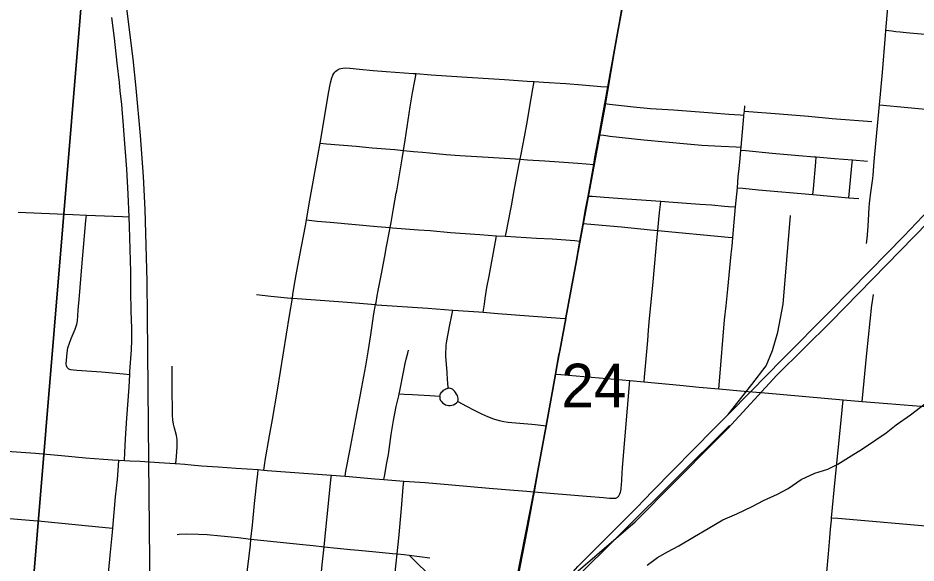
# Model space of a CAD drawing. Extents: x 0 to 1067, y 0 to 440.
# Drawn here: x 348.6 to 400.3, y 135.7 to 167.1 of the extents above; entities that cross this region are included whole.
import ezdxf

# ---------------------------------------------------------------- set-up
doc = ezdxf.new("R2010")
doc.units = 0
for name, color, linetype in [('Default', 7, 'Continuous'), ('GM_X_City_Street', 7, 'Continuous'), ('GM_X_Minor_River', 7, 'Continuous'), ('GM_X_Rail_Line', 7, 'Continuous'), ('GM_X_Section', 7, 'Continuous'), ('GM_X_Section_Text', 7, 'Continuous'), ('GM_X_US_Route', 7, 'Continuous')]:
    doc.layers.add(name, color=color, linetype=linetype)

msp = doc.modelspace()

# ---------------------------------------------------------------- linework, layer by layer
at = {"layer": 'Default'}
for points in [[(383.538, 168.597), (383.153, 166.431), (382.55, 163.126), (382.375, 162.166), (382.243, 161.443), (382.049, 160.376), (381.811, 159.058), (381.741, 158.671), (381.413, 156.85), (381.256, 155.976), (381.129, 155.274), (380.944, 154.262), (380.743, 153.151), (380.135, 149.851), (380.126, 149.804), (379.785, 147.945), (379.742, 147.712)], [(379.742, 147.712), (379.542, 146.607), (379.384, 145.736), (379.002, 143.629), (378.534, 141.049), (378.311, 139.839), (378.257, 139.545), (377.888, 137.567), (377.514, 135.589), (377.361, 134.784), (377.174, 133.774), (377.049, 133.098), (376.913, 132.365), (376.752, 131.513), (376.559, 130.556), (376.489, 130.238), (376.345, 129.588), (376.17, 128.796), (376.116, 128.559)]]:
    msp.add_lwpolyline(points, dxfattribs=at)
at = {"layer": 'GM_X_City_Street'}
for p, q in [((383.819, 146.248), (384.641, 146.171)), ((391.585, 145.523), (396.085, 145.133)), ((396.085, 145.133), (397.164, 145.035))]:
    msp.add_line(p, q, dxfattribs=at)
for points in [[(397.42, 154.116), (397.459, 154.413), (397.5, 154.855), (397.534, 155.438), (397.554, 155.842), (397.579, 156.174), (397.603, 156.432), (397.632, 156.727), (397.653, 156.911), (397.728, 157.46), (397.779, 157.864), (397.797, 158.049), (397.86, 158.829), (397.973, 160.09), (398.165, 162.1), (398.341, 163.948), (398.511, 166.102), (398.535, 166.376), (398.766, 169.034), (398.795, 169.336), (399.007, 171.556), (399.088, 172.671), (399.285, 174.937), (399.299, 175.099)], [(354.761, 141.641), (354.783, 142.094), (354.821, 142.876), (354.895, 144.069), (355.028, 145.853), (355.065, 146.588), (355.074, 146.751), (355.168, 148.011), (355.189, 148.567), (355.182, 149.235), (355.14, 150.242), (355.124, 151.362), (355.118, 152.481), (355.055, 155.09), (355.033, 155.659), (354.983, 156.952), (354.892, 158.403), (354.742, 160.374), (354.68, 161.154), (354.643, 161.599), (354.6, 162.119), (354.522, 162.896), (354.468, 163.377), (354.346, 164.489), (354.187, 165.932), (354.03, 167.113)], [(401.848, 166.045), (399.699, 166.237), (399.364, 166.272), (399.109, 166.3), (398.876, 166.329), (398.535, 166.376)], [(367.047, 164.138), (367.124, 164.173), (367.208, 164.194), (367.314, 164.212), (367.462, 164.219), (367.719, 164.211), (368.274, 164.153), (369.056, 164.077), (369.8, 164.018), (371.359, 163.908), (371.527, 163.895), (372.393, 163.831), (374.157, 163.708), (375.386, 163.629), (376.613, 163.548), (377.916, 163.467), (378.309, 163.443), (378.846, 163.409), (380.144, 163.318), (381.073, 163.251), (382.153, 163.159), (382.55, 163.126)], [(362.778, 141.083), (362.836, 141.49), (362.858, 141.637), (363.095, 143.05), (363.263, 143.991), (363.554, 145.674), (364.242, 149.974), (364.413, 150.974), (364.449, 151.185), (364.526, 151.662), (364.635, 152.322), (364.847, 153.457), (365.164, 155.141), (365.224, 155.488), (365.42, 156.61), (365.828, 158.845), (366.014, 159.89), (366.155, 160.68), (366.498, 162.777), (366.609, 163.358), (366.681, 163.642), (366.746, 163.809), (366.79, 163.892), (366.853, 163.97), (366.908, 164.035), (366.983, 164.095), (367.047, 164.138)], [(367.443, 140.733), (367.496, 141.021), (367.713, 142.194), (368.058, 144.028), (368.328, 145.441), (368.408, 145.849), (368.525, 146.47), (368.641, 147.085), (368.772, 147.883), (368.927, 148.872), (369.104, 150.068), (369.199, 150.602), (369.222, 150.732), (369.296, 151.101), (369.354, 151.424), (369.545, 152.369), (369.737, 153.393), (369.831, 153.944), (369.993, 154.823), (370.034, 155.033), (370.092, 155.335), (370.152, 155.664), (370.234, 156.139), (370.385, 157.018), (370.413, 157.159), (370.573, 158.071), (370.732, 158.989), (370.811, 159.471), (370.908, 160.056), (371.193, 161.973), (371.326, 162.782), (371.452, 163.48), (371.527, 163.895)], [(376.667, 154.532), (376.739, 154.9), (376.782, 155.12), (377.009, 156.292), (377.16, 157.175), (377.435, 158.605), (377.511, 158.974), (377.572, 159.263), (377.755, 160.254), (377.884, 160.989), (378.136, 162.462), (378.233, 163.012), (378.309, 163.443)], [(382.375, 162.166), (382.652, 162.136), (384.032, 161.987), (384.994, 161.895), (386.335, 161.807), (388.568, 161.64), (389.5, 161.568), (390.167, 161.518), (390.377, 161.502)], [(388.931, 145.758), (388.967, 146.191), (389.264, 149.721), (389.348, 150.536), (389.447, 151.501), (389.639, 153.504), (389.691, 153.959), (389.732, 154.467), (389.896, 156.227), (389.998, 157.325), (390.051, 157.98), (390.095, 158.423), (390.155, 159.012), (390.198, 159.491), (390.213, 159.66), (390.37, 161.427), (390.377, 161.502), (390.398, 161.736), (390.425, 162.047)], [(390.398, 161.736), (392.412, 161.588), (394.081, 161.437), (395.453, 161.318), (397.724, 161.146)], [(398.165, 162.1), (401.435, 161.798)], [(382.049, 160.376), (382.315, 160.343), (382.664, 160.299), (384.627, 160.081), (387.114, 159.847), (387.954, 159.776), (389.074, 159.712), (389.925, 159.673), (390.213, 159.66)], [(366.014, 159.89), (366.373, 159.859), (368.08, 159.711), (369.006, 159.627), (370.303, 159.519), (370.811, 159.471), (371.374, 159.417), (371.886, 159.371), (372.304, 159.333), (373.263, 159.244), (374.04, 159.185), (375.336, 159.109), (376.933, 159.017), (377.511, 158.974), (377.934, 158.942), (378.937, 158.868), (379.755, 158.813), (380.833, 158.743), (381.312, 158.705), (381.741, 158.671)], [(390.198, 159.491), (390.491, 159.462), (392.005, 159.311), (393.532, 159.189), (394.425, 159.11), (394.525, 159.102), (395.58, 159.016), (396.614, 158.932), (397.479, 158.861)], [(394.345, 156.934), (394.372, 157.255), (394.5, 158.8), (394.525, 159.102)], [(396.409, 156.752), (396.446, 157.144), (396.582, 158.593), (396.614, 158.932)], [(389.998, 157.325), (390.31, 157.296), (391.203, 157.211), (394.345, 156.934), (396.409, 156.752), (396.972, 156.703)], [(381.413, 156.85), (381.646, 156.836), (382.347, 156.793), (383.647, 156.69), (385.601, 156.557), (386.062, 156.525), (387.845, 156.392), (388.513, 156.337), (389.255, 156.273), (389.478, 156.257), (389.896, 156.227)], [(384.641, 146.171), (384.664, 146.432), (384.849, 148.543), (384.893, 149.138), (384.952, 149.807), (385.146, 151.698), (385.259, 152.997), (385.371, 154.298), (385.426, 154.863), (385.489, 155.5), (385.526, 155.896), (385.58, 156.371), (385.601, 156.557)], [(348.659, 155.919), (351.802, 155.789), (352.573, 155.758), (354.641, 155.675), (355.033, 155.659)], [(351.547, 146.914), (351.466, 146.989), (351.419, 147.088), (351.406, 147.199), (351.463, 147.83), (351.511, 148.124), (351.696, 148.651), (351.93, 149.199), (352.026, 149.48), (352.054, 149.663), (352.098, 150.294), (352.174, 151.109), (352.315, 152.78), (352.457, 154.562), (352.543, 155.452), (352.573, 155.758)], [(365.224, 155.488), (365.69, 155.432), (365.838, 155.414), (366.581, 155.34), (369.285, 155.096), (370.034, 155.033), (370.176, 155.021), (371.66, 154.912), (372.328, 154.862), (373.514, 154.755), (375.183, 154.628), (376.15, 154.563), (376.667, 154.532), (377.264, 154.496), (378.454, 154.436), (379.345, 154.386), (380.657, 154.284), (380.944, 154.262)], [(381.129, 155.274), (381.346, 155.255), (383.339, 155.08), (385.01, 154.907), (385.426, 154.863), (389.472, 154.491), (389.732, 154.467)], [(375.374, 150.161), (375.434, 150.511), (375.452, 150.621), (375.506, 150.952), (375.602, 151.58), (375.725, 152.241), (376.088, 154.227), (376.15, 154.563)], [(362.354, 151.178), (363.174, 151.093), (364.323, 150.983), (364.413, 150.974), (367.071, 150.774), (367.815, 150.717), (369.199, 150.602), (369.263, 150.597), (372.202, 150.402), (373.631, 150.291), (375.14, 150.181), (375.374, 150.161), (376.217, 150.089), (378.002, 149.952), (379.815, 149.825), (380.126, 149.804)], [(397.164, 145.035), (397.433, 147.809), (397.727, 150.576), (397.76, 150.785), (397.786, 150.927), (397.803, 151.055), (397.822, 151.195)], [(373.25, 148.096), (373.265, 148.258), (373.284, 148.407), (373.454, 149.353), (373.578, 150.006), (373.631, 150.291)], [(369.677, 140.537), (369.726, 140.814), (369.83, 141.4), (369.933, 141.986), (370.1, 143.127), (370.193, 143.715), (370.227, 143.935), (370.304, 144.331), (370.384, 144.737), (370.532, 145.351), (370.559, 145.474), (370.595, 145.642), (370.812, 146.711), (370.906, 147.207), (370.962, 147.459), (371.043, 147.814), (371.084, 147.986)], [(373.917, 145.027), (373.939, 145.121), (373.939, 145.21), (373.923, 145.287), (373.901, 145.367), (373.856, 145.453), (373.796, 145.547), (373.74, 145.619), (373.685, 145.68), (373.613, 145.735), (373.565, 145.763), (373.498, 145.785), (373.436, 145.795), (373.37, 145.795), (373.353, 146.114), (373.335, 146.284), (373.31, 146.691), (373.243, 147.632), (373.243, 147.867), (373.25, 148.096)], [(351.547, 146.914), (351.656, 146.875), (351.84, 146.855), (352.028, 146.842), (353.444, 146.734), (354.697, 146.622), (355.065, 146.588)], [(357.715, 141.457), (357.751, 141.858), (357.8, 142.414), (357.8, 142.667), (357.783, 142.85), (357.746, 143.067), (357.616, 143.575), (357.586, 143.723), (357.543, 143.985), (357.529, 144.249), (357.507, 145.934), (357.497, 147.056)], [(379.542, 146.607), (379.856, 146.58), (383.819, 146.248)], [(383.089, 139.511), (383.129, 139.541), (383.162, 139.573), (383.207, 139.641), (383.246, 139.719), (383.28, 139.809), (383.299, 139.894), (383.314, 139.978), (383.326, 140.084), (383.336, 140.207), (383.389, 141.239), (383.819, 146.248)], [(384.641, 146.171), (386.691, 145.979), (387.794, 145.861), (388.931, 145.758)], [(372.884, 145.337), (372.904, 145.416), (372.932, 145.478), (372.962, 145.523), (373.011, 145.58), (373.055, 145.624), (373.11, 145.674), (373.177, 145.718), (373.237, 145.757), (373.304, 145.784), (373.37, 145.795)], [(388.931, 145.758), (390.388, 145.626), (391.585, 145.523)], [(370.559, 145.474), (370.833, 145.458), (371.317, 145.431), (372.315, 145.381), (372.884, 145.337), (372.884, 145.271), (372.9, 145.188), (372.939, 145.094), (372.989, 145.022), (373.053, 144.95), (373.143, 144.889), (373.221, 144.845), (373.304, 144.818), (373.392, 144.801), (373.48, 144.801), (373.583, 144.812), (373.68, 144.842), (373.779, 144.889), (373.851, 144.945), (373.917, 145.027), (374.182, 144.895), (374.427, 144.766), (374.857, 144.539), (375.284, 144.312), (375.624, 144.161), (375.972, 144.028), (376.295, 143.935), (376.567, 143.877), (376.825, 143.835), (377.031, 143.815), (378.184, 143.722), (378.37, 143.702), (378.546, 143.682), (379.002, 143.629)], [(394.854, 131.975), (394.877, 132.22), (395.027, 133.828), (395.169, 135.422), (395.238, 136.262), (395.308, 137.179), (395.344, 137.694), (395.406, 138.21), (395.418, 138.347), (395.625, 140.528), (395.961, 143.933), (396.085, 145.133)], [(397.164, 145.035), (398.622, 144.91), (401.988, 144.639), (403.61, 144.497), (406.184, 144.271)], [(346.603, 142.271), (348.831, 142.122), (349.649, 142.056), (351.133, 141.923), (352.528, 141.788), (354.07, 141.675), (354.441, 141.657), (354.761, 141.641), (355.075, 141.625), (355.67, 141.593), (356.748, 141.525), (357.674, 141.46), (357.715, 141.457), (358.223, 141.417), (358.593, 141.385), (359.183, 141.334), (360.147, 141.272), (361.191, 141.196), (362.452, 141.109), (362.778, 141.083), (362.971, 141.068), (366.659, 140.791), (367.443, 140.733), (367.675, 140.713), (369.158, 140.576), (369.677, 140.537), (370.817, 140.452), (372.057, 140.362), (373.577, 140.227), (375.732, 140.044), (377.142, 139.931), (377.887, 139.873), (378.311, 139.839)], [(352.306, 118.96), (352.323, 119.189), (352.375, 119.899), (352.503, 121.16), (352.618, 122.271), (352.678, 122.924), (352.693, 123.087), (352.853, 124.905), (353.016, 126.572), (353.117, 127.608), (353.216, 128.647), (353.298, 129.499), (353.449, 131.13), (353.546, 132.206), (353.686, 133.531), (353.703, 133.689), (353.938, 136.172), (354.068, 137.506), (354.09, 137.748), (354.253, 139.547), (354.355, 140.548), (354.416, 141.332), (354.441, 141.657)], [(361.766, 134.739), (361.998, 136.788), (362.034, 137.11), (362.123, 137.919), (362.238, 139.162), (362.393, 140.563), (362.423, 140.842), (362.452, 141.109)], [(364.764, 121.631), (364.785, 121.875), (364.865, 122.791), (364.869, 122.831), (364.89, 123.218), (364.96, 124.109), (365.071, 125.258), (365.212, 126.629), (365.296, 127.562), (365.309, 127.705), (365.367, 128.272), (365.533, 129.889), (365.743, 131.849), (365.813, 132.503), (365.963, 133.886), (366.133, 135.626), (366.236, 136.674), (366.354, 137.865), (366.457, 138.781), (366.632, 140.525), (366.659, 140.791)], [(369.35, 132.081), (369.636, 132.347), (369.786, 132.513), (369.923, 132.69), (370, 132.818), (370.06, 132.954), (370.097, 133.068), (370.123, 133.167), (370.163, 133.387), (370.311, 135.022), (370.381, 135.727), (370.436, 136.263), (370.528, 137.175), (370.683, 138.884), (370.788, 140.109), (370.817, 140.452)], [(378.311, 139.839), (381.321, 139.589), (382.297, 139.5), (382.645, 139.466), (382.791, 139.461), (382.864, 139.461), (382.932, 139.465), (383.01, 139.478), (383.053, 139.492), (383.089, 139.511)], [(335.65, 139.404), (335.951, 139.377), (339.567, 139.051), (340.386, 138.984), (340.511, 138.974), (340.978, 138.936), (342.092, 138.84), (344.018, 138.654), (349.998, 138.146), (353.662, 137.79), (354.09, 137.748)], [(395.418, 138.347), (395.767, 138.317), (397.328, 138.185), (402.576, 137.729), (403.985, 137.62), (405.558, 137.468), (406.789, 137.35), (408.315, 137.216), (408.613, 137.201), (408.945, 137.206), (409.064, 137.219), (409.195, 137.252), (409.277, 137.301)], [(357.8, 137.375), (357.903, 137.391), (358.305, 137.41), (359.008, 137.401), (359.524, 137.372), (360.298, 137.31), (360.519, 137.288), (360.888, 137.248), (361.294, 137.201), (362.034, 137.11), (362.218, 137.087), (365.023, 136.8), (365.615, 136.74), (366.236, 136.674), (366.986, 136.599), (367.763, 136.52), (368.207, 136.473), (369.207, 136.373), (370.171, 136.289), (370.436, 136.263), (370.838, 136.224), (371.126, 136.188), (372.318, 136.042)], [(371.126, 136.188), (371.196, 136.121), (372.504, 134.831), (373.862, 133.451), (374.599, 132.716), (374.892, 132.451), (375.025, 132.34), (375.191, 132.212), (375.33, 132.111), (375.58, 131.985), (375.936, 131.818), (376.328, 131.671), (376.752, 131.513)]]:
    msp.add_lwpolyline(points, dxfattribs=at)
at = {"layer": 'GM_X_Minor_River'}
msp.add_lwpolyline([(384.802, 135.61), (385.396, 136.06), (385.989, 136.374), (386.627, 136.733), (387.54, 137.272), (388.315, 137.721), (389.159, 138.215), (389.957, 138.572), (390.845, 138.998), (391.507, 139.334), (392.304, 139.691), (392.92, 140.028), (393.673, 140.545), (394.448, 140.903), (395.199, 141.147), (395.768, 141.416), (396.544, 141.91), (397.183, 142.315), (397.959, 142.832), (398.553, 143.237), (399.124, 143.687), (399.946, 144.272), (400.769, 144.903)], dxfattribs=at)
at = {"layer": 'GM_X_Rail_Line'}
msp.add_line((389.553, 143.652), (378.756, 132.93), dxfattribs=at)
for points in [[(376.58, 131.044), (378.327, 140.014), (382.376, 161.87), (384, 171.502)], [(356.264, 129.575), (356.216, 135.845), (356.168, 141.611), (356.111, 147.881), (356.068, 151.953), (355.943, 156.072), (355.856, 157.983), (355.679, 160.335), (355.439, 163.053), (355.264, 164.735), (354.629, 169.803)], [(389.458, 143.485), (392.267, 146.546), (395.371, 149.61), (403.354, 157.796), (407.091, 161.624), (409.522, 164.625), (412.954, 168.924)], [(389.459, 144.278), (390.77, 145.605), (392.599, 147.461), (395.341, 150.233), (397.597, 152.528), (399.565, 154.533), (401.022, 156.077), (402.126, 157.297), (404.132, 159.609), (405.12, 160.763), (405.985, 161.836), (408.574, 165.069)], [(389.459, 144.278), (390.835, 146), (391.644, 147.085), (392.019, 147.973), (392.315, 149.019), (392.631, 150.636), (393.045, 155.726)], [(378.756, 132.93), (379.015, 133.243), (380.156, 134.762), (380.835, 135.535), (381.635, 136.353), (382.569, 137.287), (384.209, 138.923), (385.126, 139.88), (388.671, 143.48), (389.459, 144.278)], [(384.114, 138.104), (388.684, 142.711), (389.458, 143.485)], [(379.945, 134.531), (381.122, 135.514), (384.114, 138.104)]]:
    msp.add_lwpolyline(points, dxfattribs=at)
at = {"layer": 'GM_X_Section'}
for points in [[(293.305, 184.745), (353.183, 178.942), (348.264, 119.585), (289.359, 125.481)], [(353.183, 178.942), (415.565, 173.729), (410.18, 114.397), (348.264, 119.585)]]:
    msp.add_lwpolyline(points, close=True, dxfattribs=at)
at = {"layer": 'GM_X_US_Route'}
for points in [[(379.742, 147.712), (379.785, 147.945), (380.126, 149.804), (380.135, 149.851), (380.743, 153.151), (380.944, 154.262), (381.129, 155.274), (381.256, 155.976), (381.413, 156.85), (381.741, 158.671), (381.811, 159.058), (382.049, 160.376), (382.243, 161.443), (382.375, 162.166), (382.55, 163.126), (383.153, 166.431), (383.538, 168.597)], [(376.116, 128.559), (376.17, 128.796), (376.345, 129.588), (376.489, 130.238), (376.559, 130.556), (376.752, 131.513), (376.913, 132.365), (377.049, 133.098), (377.174, 133.774), (377.361, 134.784), (377.514, 135.589), (377.888, 137.567), (378.257, 139.545), (378.311, 139.839), (378.534, 141.049), (379.002, 143.629), (379.384, 145.736), (379.542, 146.607), (379.742, 147.712)]]:
    msp.add_lwpolyline(points, dxfattribs=at)

# ---------------------------------------------------------------- texts
at = {"layer": 'GM_X_Section_Text'}
msp.add_text('24', height=2.5114, rotation=0, dxfattribs=at).set_placement((379.879, 144.695))

doc.saveas('drawing.dxf')
